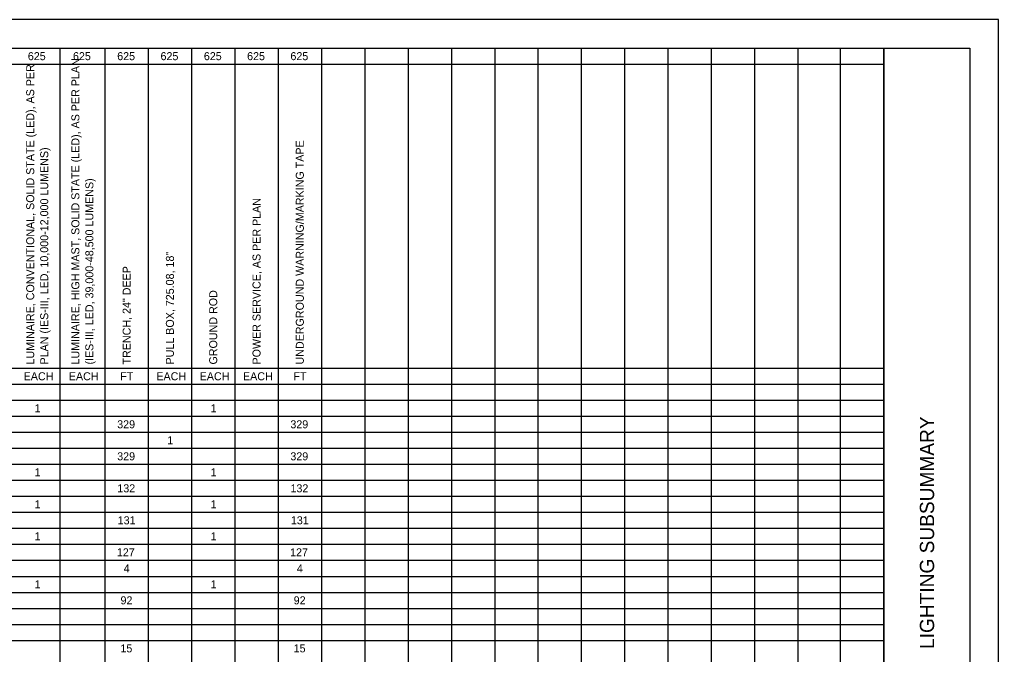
# Model space of a CAD drawing. Extents: x 0 to 34, y 0 to 22.
# Drawn here: x 16.87 to 34, y 10.89 to 22 of the extents above; entities that cross this region are included whole.
import ezdxf

# ---------------------------------------------------------------- set-up
doc = ezdxf.new("R2010")
doc.units = 0
for name, color, linetype in [('SH_Border', 7, 'Continuous'), ('SH_Cut_Line', 7, 'Continuous'), ('SH_Data', 7, 'Continuous'), ('SH_Text', 7, 'Continuous')]:
    doc.layers.add(name, color=color, linetype=linetype)

msp = doc.modelspace()

# ---------------------------------------------------------------- linework, layer by layer
at = {"layer": 'SH_Border'}
msp.add_line((32, 0.5), (32, 21.5), dxfattribs=at)
msp.add_lwpolyline([(1.5, 21.5), (33.5, 21.5), (33.5, 0.5), (1.5, 0.5)], close=True, dxfattribs=at)
at = {"layer": 'SH_Cut_Line'}
msp.add_lwpolyline([(0, 0), (34, 0), (34, 22), (0, 22)], close=True, dxfattribs=at)
at = {"layer": 'SH_Text'}
for p, q in [((1.5, 21.5), (31.987, 21.5)), ((17.575, 21.5), (17.575, 0.5)), ((18.366, 21.5), (18.366, 0.5)), ((19.124, 21.5), (19.124, 0.5)), ((19.881, 21.5), (19.881, 0.5)), ((20.639, 21.5), (20.639, 0.5)), ((21.396, 21.5), (21.396, 0.5)), ((22.154, 21.5), (22.154, 0.5)), ((22.912, 21.5), (22.912, 0.5)), ((23.669, 21.5), (23.669, 0.5)), ((24.427, 21.5), (24.427, 0.5)), ((25.185, 21.5), (25.185, 0.5)), ((25.942, 21.5), (25.942, 0.5)), ((26.7, 21.5), (26.7, 0.5)), ((27.458, 21.5), (27.458, 0.5)), ((28.215, 21.5), (28.215, 0.5)), ((28.973, 21.5), (28.973, 0.5)), ((29.731, 21.5), (29.731, 0.5)), ((30.488, 21.5), (30.488, 0.5)), ((31.229, 21.5), (31.229, 0.5)), ((31.987, 21.5), (31.987, 0.5)), ((8.451, 21.22), (31.987, 21.22)), ((8.451, 15.9), (31.987, 15.9)), ((1.5, 15.62), (31.987, 15.62)), ((1.5, 15.34), (31.987, 15.34)), ((1.5, 15.06), (31.987, 15.06)), ((1.5, 14.78), (31.987, 14.78)), ((1.5, 14.5), (31.987, 14.5)), ((1.5, 14.22), (31.987, 14.22)), ((1.5, 13.94), (31.987, 13.94)), ((1.5, 13.66), (31.987, 13.66)), ((1.5, 13.38), (31.987, 13.38)), ((1.5, 13.1), (31.987, 13.1)), ((1.5, 12.82), (31.987, 12.82)), ((1.5, 12.54), (31.987, 12.54)), ((1.5, 12.26), (31.987, 12.26)), ((1.5, 11.98), (31.987, 11.98)), ((1.5, 11.7), (31.987, 11.7)), ((1.5, 11.42), (31.987, 11.42)), ((1.5, 11.14), (31.987, 11.14))]:
    msp.add_line(p, q, dxfattribs=at)

# ---------------------------------------------------------------- texts
at = {"layer": 'SH_Data'}
msp.add_text('LIGHTING SUBSUMMARY', height=0.25, rotation=90, dxfattribs=at).set_placement((32.875, 10.99))
at = {"layer": 'SH_Text'}
for s, p in [('625', (17.016, 21.29)), ('625', (17.806, 21.29)), ('625', (18.58, 21.29)), ('625', (19.338, 21.29)), ('625', (20.096, 21.29)), ('625', (20.853, 21.29)), ('625', (21.611, 21.29)), ('EACH', (16.943, 15.69)), ('EACH', (17.733, 15.69)), ('FT', (18.633, 15.69)), ('EACH', (19.265, 15.69)), ('EACH', (20.023, 15.69)), ('EACH', (20.781, 15.69)), ('FT', (21.664, 15.69)), ('1', (17.135, 15.13)), ('1', (20.215, 15.13)), ('329', (18.58, 14.85)), ('329', (21.61, 14.85)), ('1', (19.457, 14.57)), ('329', (18.58, 14.29)), ('329', (21.61, 14.29)), ('1', (17.135, 14.01)), ('1', (20.215, 14.01)), ('132', (18.582, 13.73)), ('132', (21.612, 13.73)), ('1', (17.135, 13.45)), ('1', (20.215, 13.45)), ('131', (18.588, 13.17)), ('131', (21.619, 13.17)), ('1', (17.135, 12.89)), ('1', (20.215, 12.89)), ('127', (18.574, 12.61)), ('127', (21.605, 12.61)), ('4', (18.694, 12.33)), ('4', (21.724, 12.33)), ('1', (17.135, 12.05)), ('1', (20.215, 12.05)), ('92', (18.638, 11.77)), ('92', (21.668, 11.77)), ('15', (18.636, 10.93)), ('15', (21.667, 10.93))]:
    msp.add_text(s, height=0.14, dxfattribs=at).set_placement(p)
for s, p in [('LUMINAIRE, HIGH MAST, SOLID STATE (LED), AS PER PLAN ', (17.918, 15.966)), ('LUMINAIRE, CONVENTIONAL, SOLID STATE (LED), AS PER ', (17.128, 15.966)), ('UNDERGROUND WARNING/MARKING TAPE', (21.845, 15.966)), ('PLAN (IES-III, LED, 10,000-12,000 LUMENS)', (17.373, 15.966)), ('(IES-III, LED, 39,000-48,500 LUMENS)', (18.163, 15.966)), ('POWER SERVICE, AS PER PLAN', (21.088, 15.966)), ('PULL BOX, 725.08, 18"', (19.572, 15.966)), ('TRENCH, 24" DEEP', (18.815, 15.966)), ('GROUND ROD', (20.33, 15.966))]:
    msp.add_text(s, height=0.14, rotation=90, dxfattribs=at).set_placement(p)

doc.saveas('drawing.dxf')
